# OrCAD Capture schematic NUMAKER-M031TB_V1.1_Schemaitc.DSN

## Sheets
1 Nu-Link2-Me: size A3; title: Nu-Link2-Me; rev: 1.0; company: CMHuang; note: Nu-Link2-Me
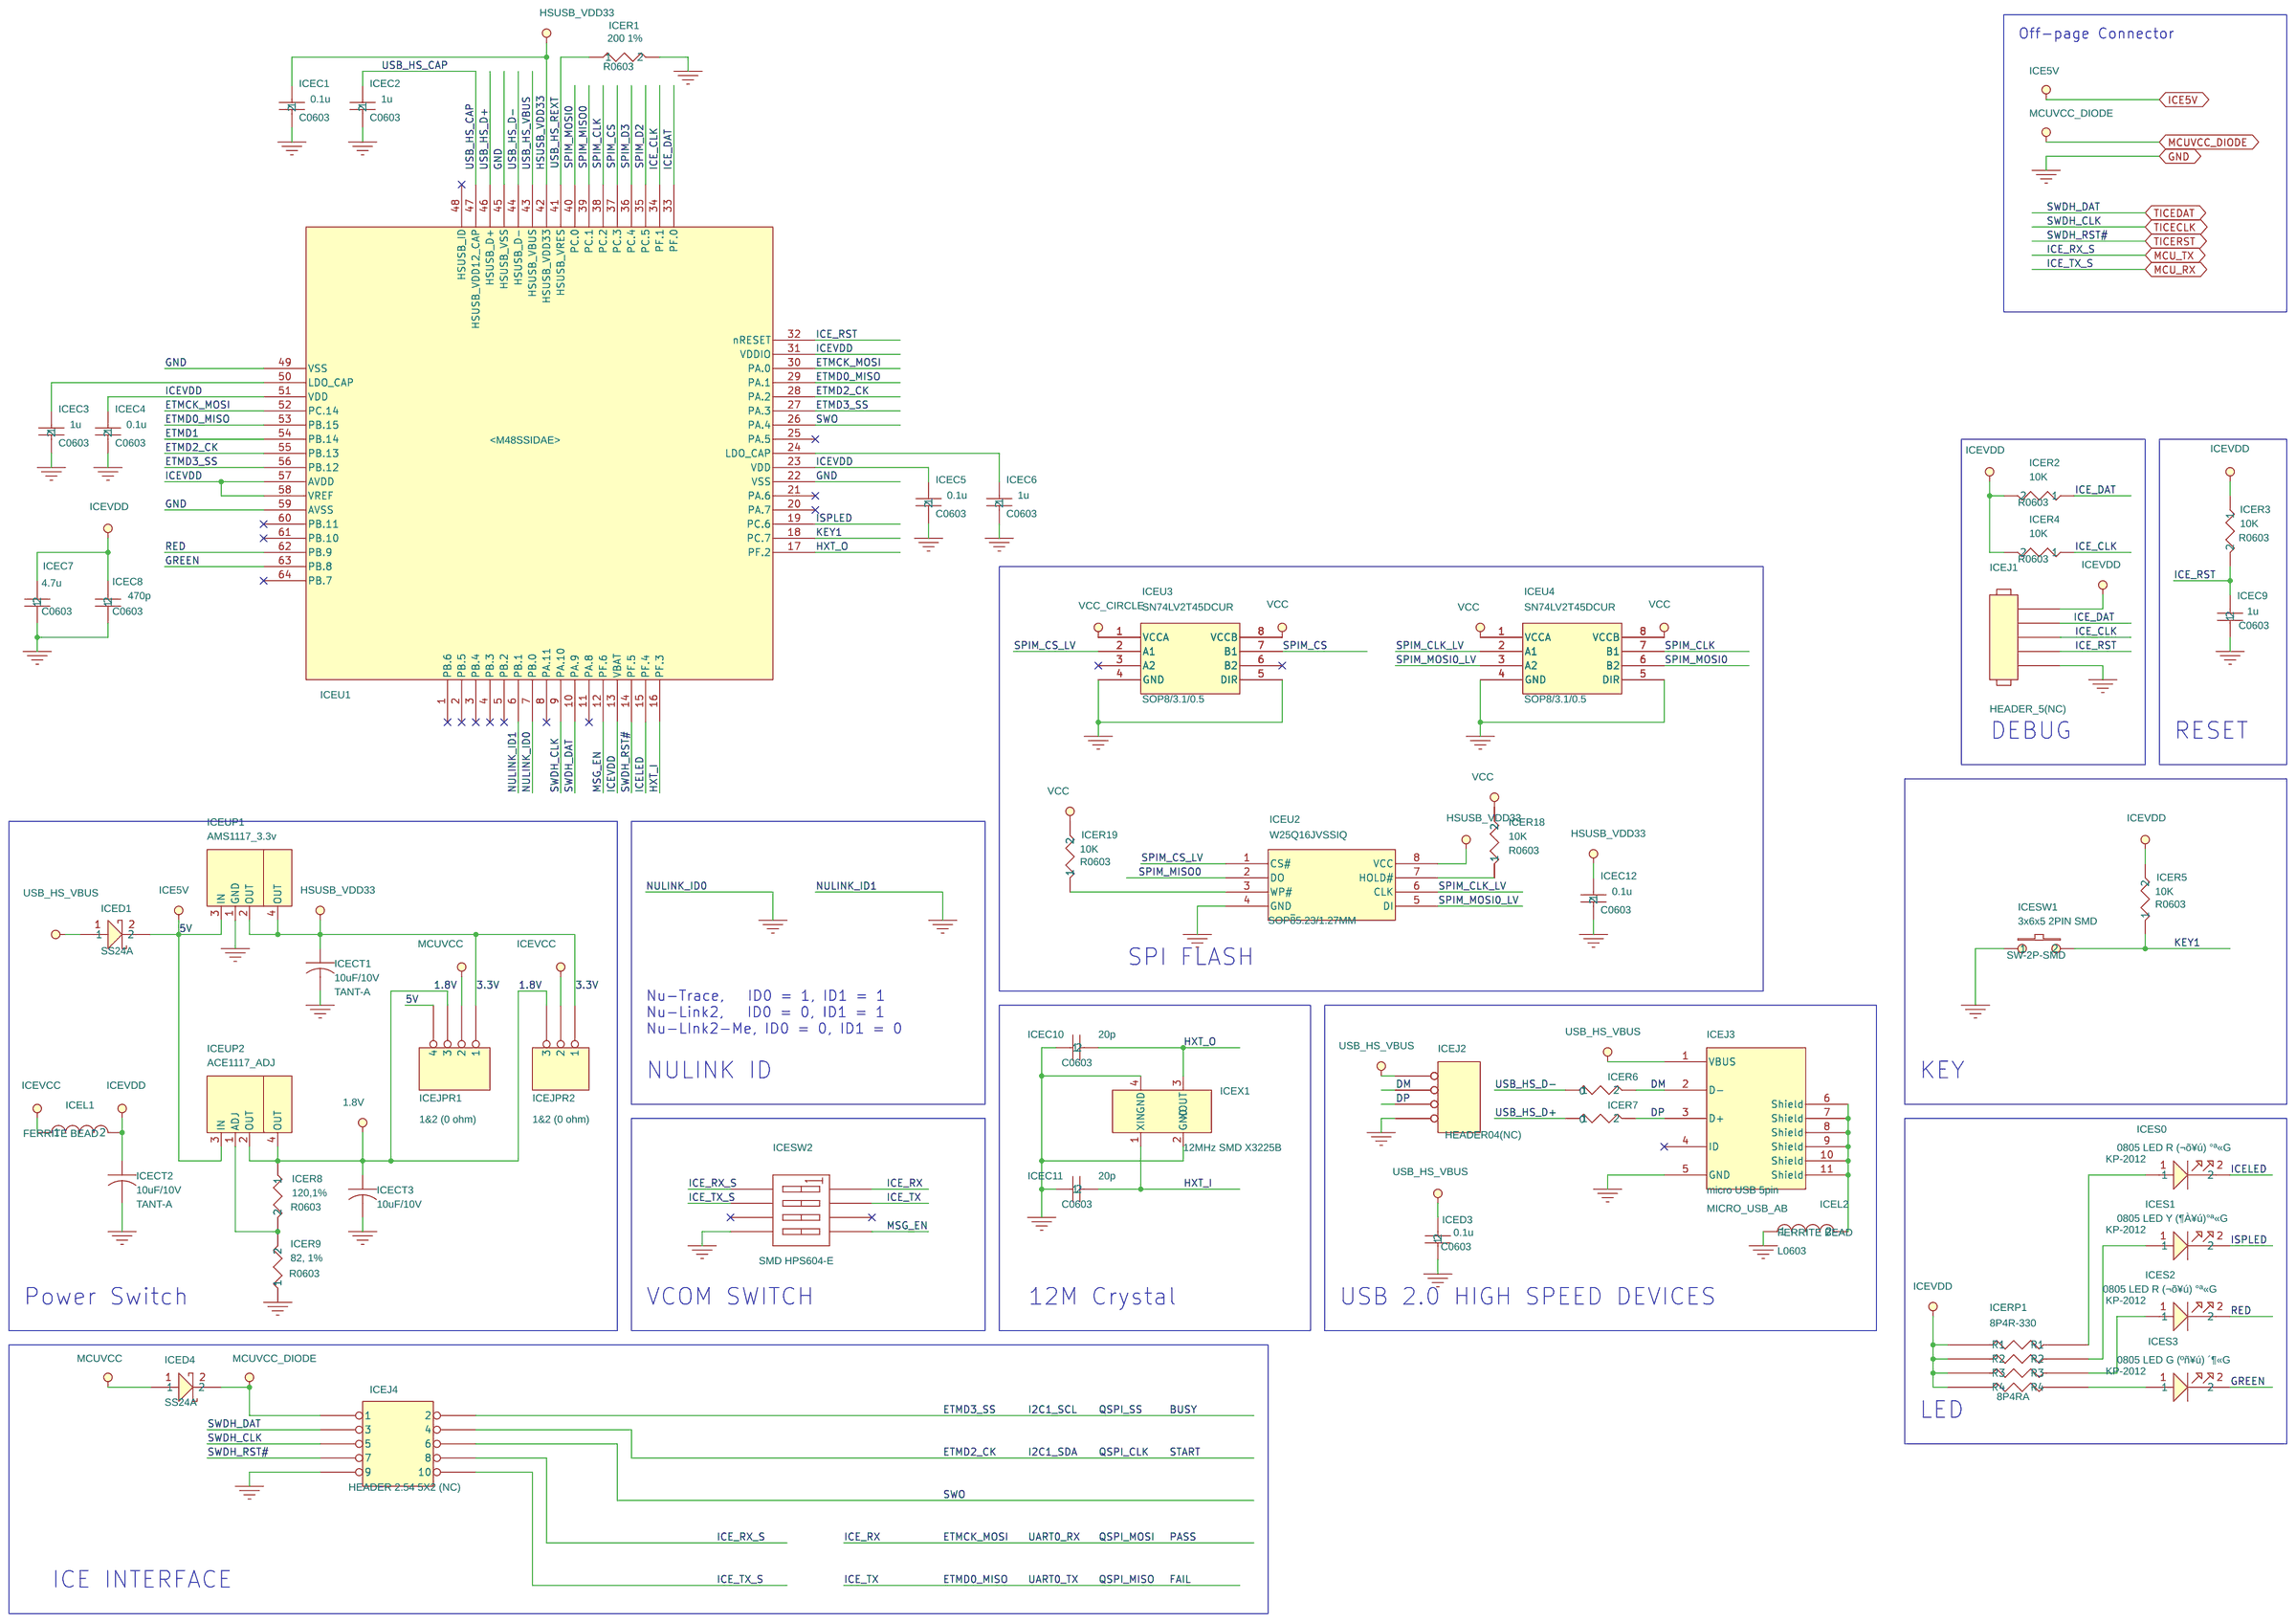
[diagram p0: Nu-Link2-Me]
2 M031TB0AE: size Custom; title: M031TB0AE; rev: v1.1; note: NuMaker-M031TB
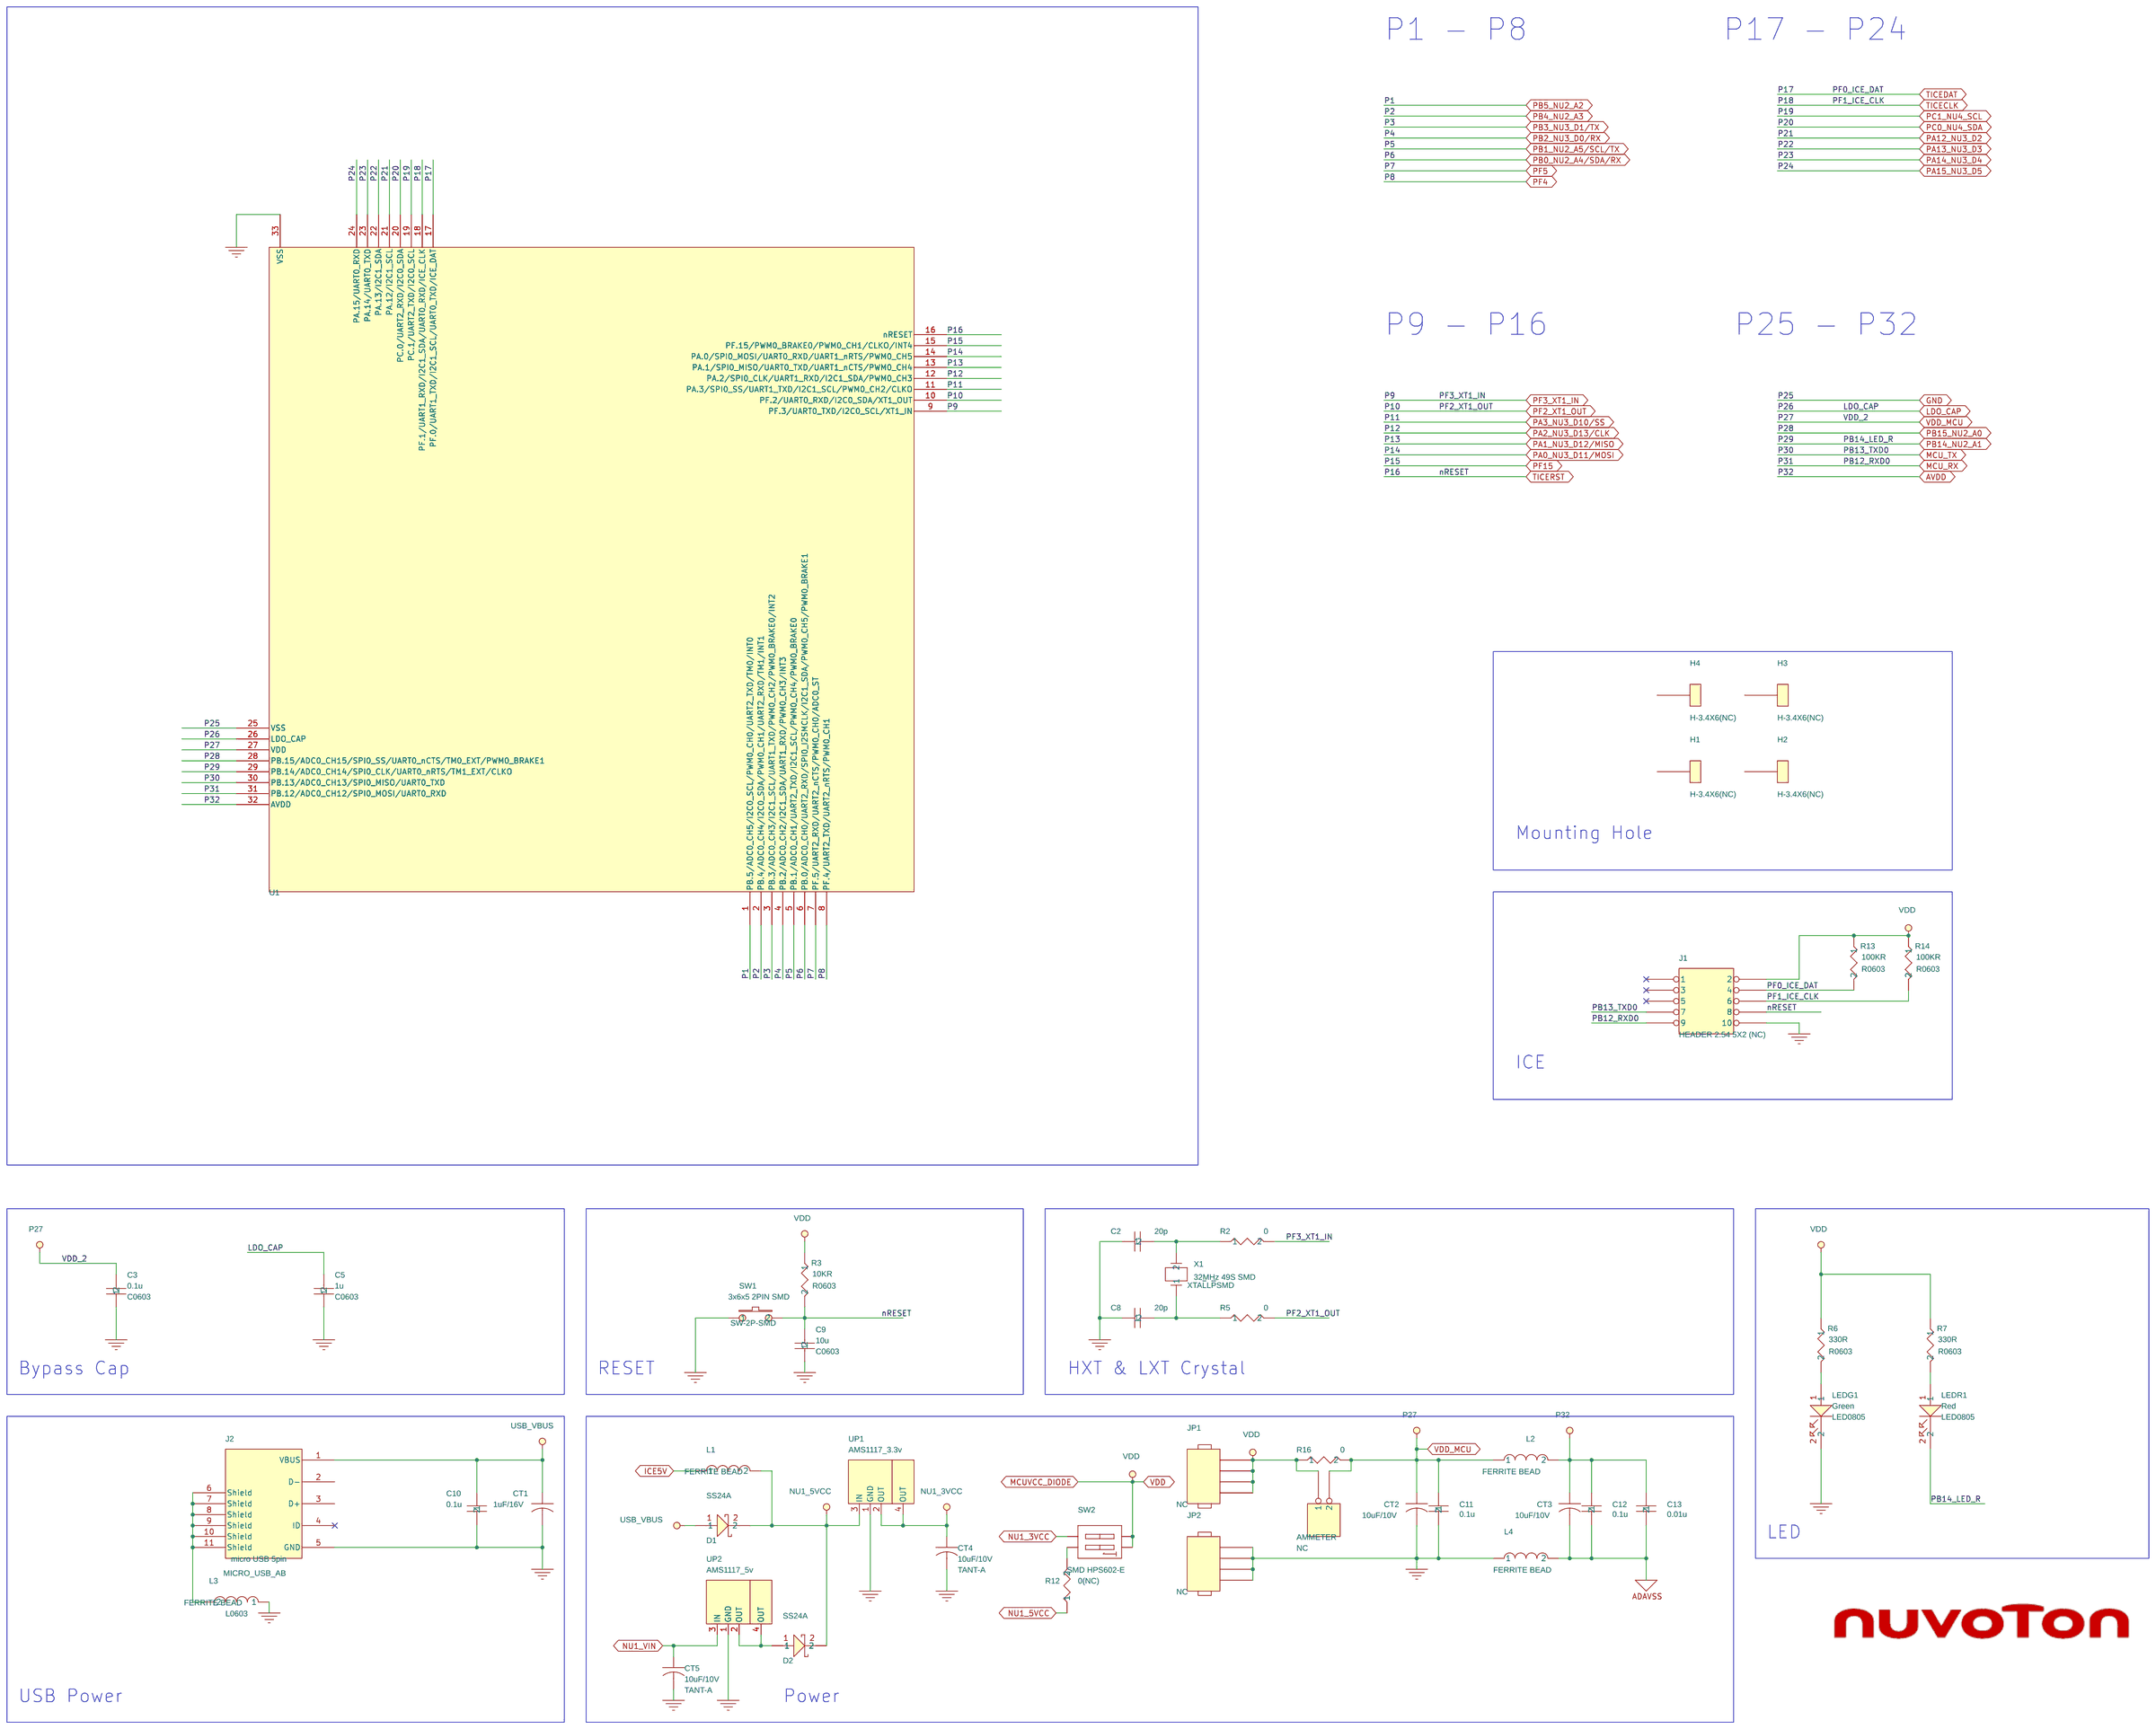
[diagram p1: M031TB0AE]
3 Ext. Connector: size Custom; title: Ext. Connector; rev: v1.1; note: NuMaker-M031TB
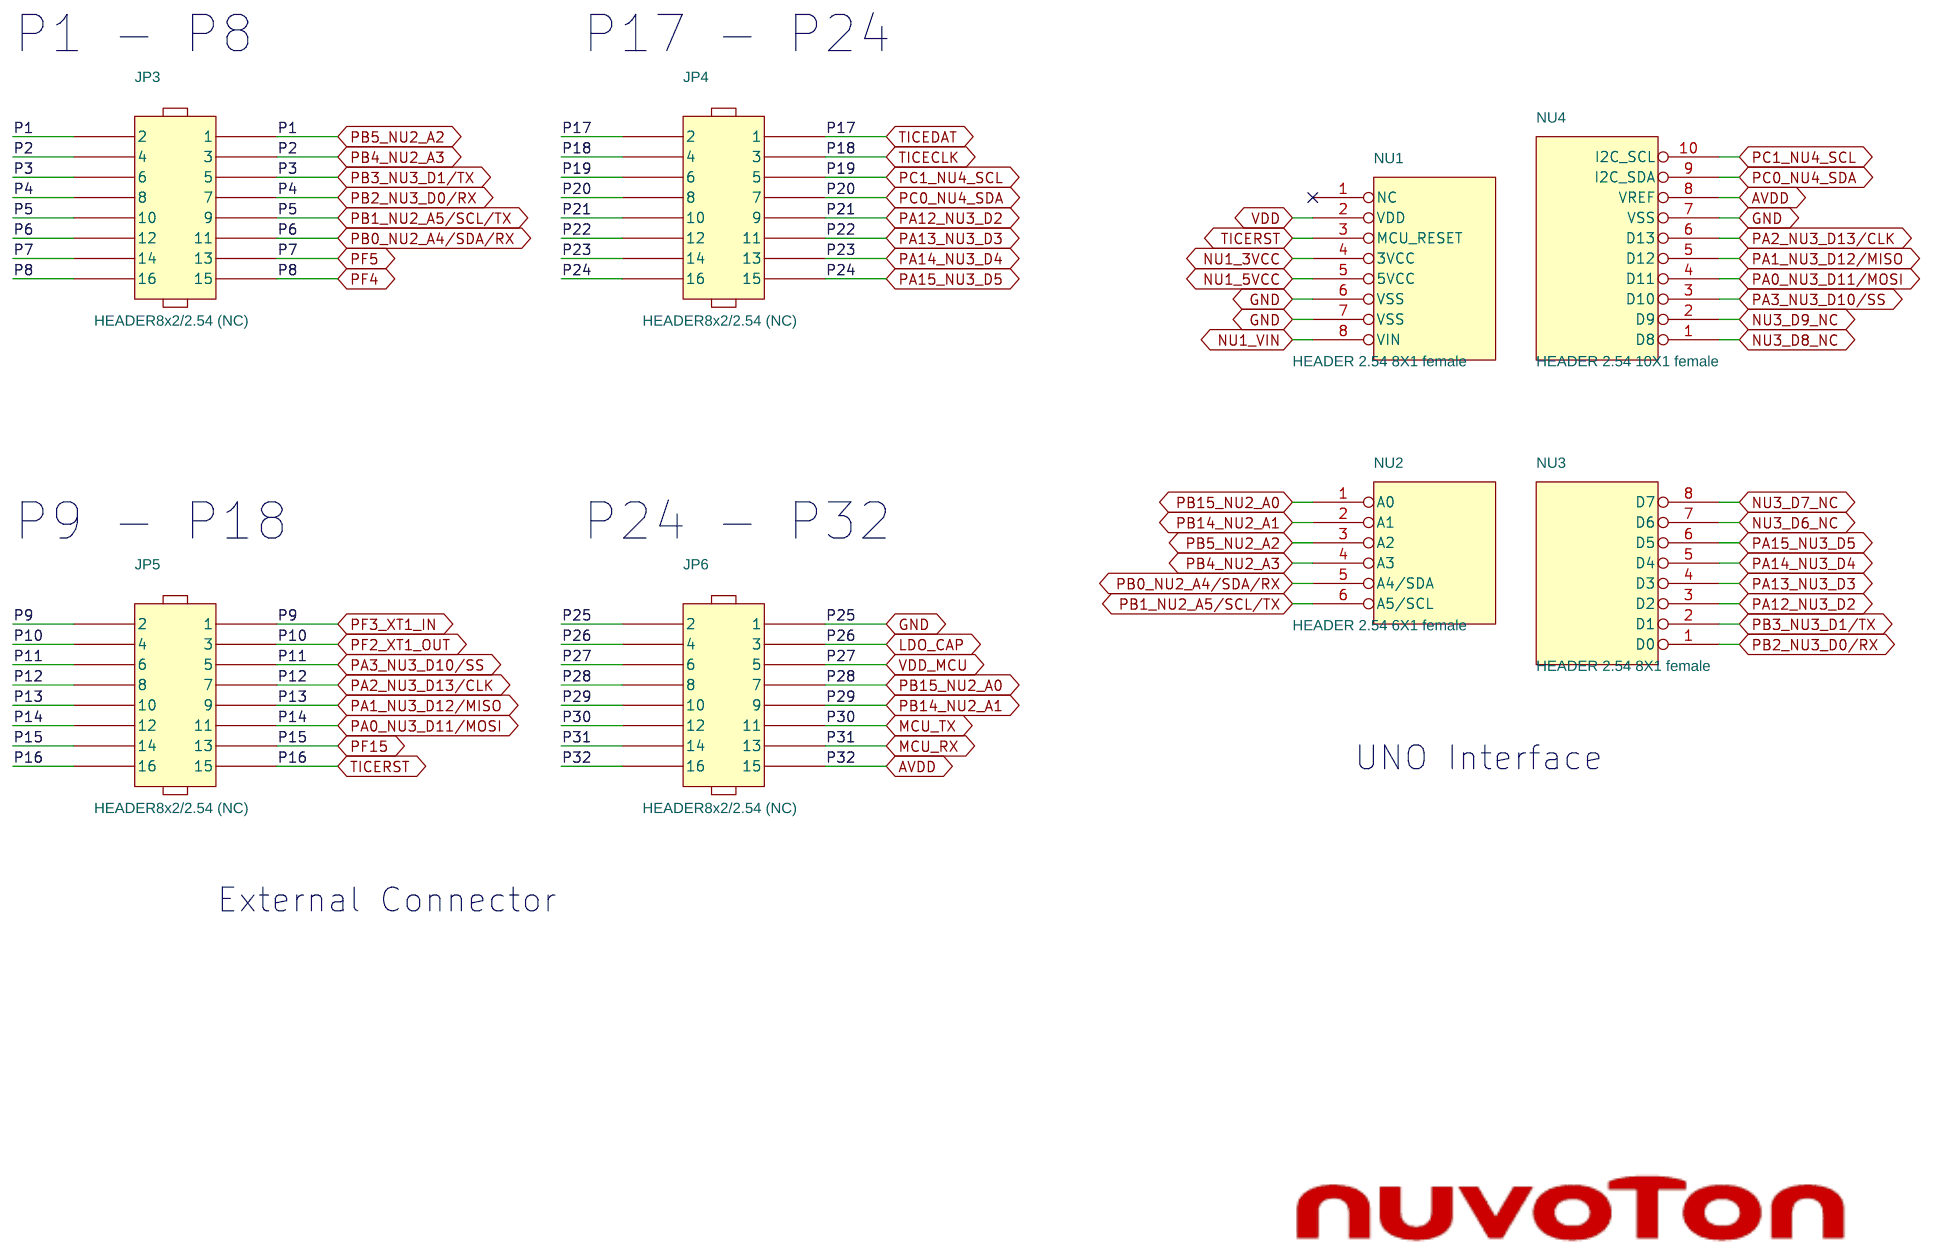
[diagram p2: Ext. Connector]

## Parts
sheet Ext. Connector
JP3  HEADER8x2/2.54 (NC)  [HEADER8x2/2.54]
JP4  HEADER8x2/2.54 (NC)  [HEADER8x2/2.54]
JP5  HEADER8x2/2.54 (NC)  [HEADER8x2/2.54]
JP6  HEADER8x2/2.54 (NC)  [HEADER8x2/2.54]
NU1  HEADER 2.54 8X1 female  [SIP-8P]
NU2  HEADER 2.54 6X1 female  [SIP-6P]
NU3  HEADER 2.54 8X1 female  [SIP-8P]
NU4  HEADER 2.54 10X1 female  [SIP-10P]
sheet M031TB0AE
AMMETER  NC  [HEADER2X1]
C2  20p  [C0603]
C3  0.1u  [C0603]
C5  1u  [C0603]
C8  20p  [C0603]
C9  10u  [C0603]
C10  0.1u  [C0603]
C11  0.1u  [C0603]
C12  0.1u  [C0603]
C13  0.01u  [C0603]
CT1  1uF/16V  [TANT-A]
CT2  10uF/10V  [TANT-A]
CT3  10uF/10V  [TANT-A]
CT4  10uF/10V  [TANT-A]
CT5  10uF/10V  [TANT-A]
D1  SS24A  [RB060L]
D2  SS24A  [RB060L]
H1  H-3.4X6(NC)  [H-3.4X6]
H2  H-3.4X6(NC)  [H-3.4X6]
H3  H-3.4X6(NC)  [H-3.4X6]
H4  H-3.4X6(NC)  [H-3.4X6]
J1  HEADER 2.54 5X2 (NC)  [HEADER5X2]
J2  micro USB 5pin  [MICRO_USB_AB]
JP1  NC  [header1x4]
JP2  NC  [header1x4]
L1  FERRITE BEAD  [L0603]
L2  FERRITE BEAD  [L0603]
L3  FERRITE BEAD  [L0603]
L4  FERRITE BEAD  [L0603]
LEDG1  Green  [LED0805]
LEDR1  Red  [LED0805]
R2  0  [R0603]
R3  10KR  [R0603]
R5  0  [R0603]
R6  330R  [R0603]
R7  330R  [R0603]
R12  0(NC)  [R0603]
R13  100KR  [R0603]
R14  100KR  [R0603]
R16  0  [R0603]
SW1  3x6x5 2PIN SMD  [SW-2P-SMD]
SW2  SMD HPS602-E  [SW1X2]
U1  M031TB0AE  [MCU_QFN_33_4x4]
UP1  AMS1117_3.3v  [SOT-223-1]
UP2  AMS1117_5v  [SOT-223-1]
X1  32MHz 49S SMD  [XTAL\LP\SMD]
sheet Nu-Link2-Me
ICEC1  0.1u  [C0603]
ICEC2  1u  [C0603]
ICEC3  1u  [C0603]
ICEC4  0.1u  [C0603]
ICEC5  0.1u  [C0603]
ICEC6  1u  [C0603]
ICEC7  4.7u  [C0603]
ICEC8  470p  [C0603]
ICEC9  1u  [C0603]
ICEC10  20p  [C0603]
ICEC11  20p  [C0603]
ICEC12  0.1u  [C0603]
ICECT1  10uF/10V  [TANT-A]
ICECT2  10uF/10V  [TANT-A]
ICECT3  10uF/10V  [TANT-A]
ICED1  SS24A  [RB060L]
ICED3  0.1u  [C0603]
ICED4  SS24A  [RB060L]
ICEJ1  HEADER_5(NC)  [HEADER5X1]
ICEJ2  HEADER04(NC)  [HEADER04]
ICEJ3  micro USB 5pin  [MICRO_USB_AB]
ICEJ4  HEADER 2.54 5X2 (NC)  [HEADER5X2]
ICEJPR1  1&2 (0 ohm)  [R0603X3]
ICEJPR2  1&2 (0 ohm)  [R0603X2]
ICEL1  FERRITE BEAD  [L0603]
ICEL2  FERRITE BEAD  [L0603]
ICER1  200 1%  [R0603]
ICER2  10K  [R0603]
ICER3  10K  [R0603]
ICER4  10K  [R0603]
ICER5  10K  [R0603]
ICER6  0  [R0603]
ICER7  0  [R0603]
ICER8  120,1%  [R0603]
ICER9  82, 1%  [R0603]
ICER18  10K  [R0603]
ICER19  10K  [R0603]
ICERP1  8P4R-330  [8P4RA]
ICES0  0805 LED R (¬õ¥ú) °ª«G  [KP-2012]
ICES1  0805 LED Y (¶À¥ú)°ª«G  [KP-2012]
ICES2  0805 LED R (¬õ¥ú) °ª«G  [KP-2012]
ICES3  0805 LED G (ºñ¥ú) ´¶«G  [KP-2012]
ICESW1  3x6x5 2PIN SMD  [SW-2P-SMD]
ICESW2  SMD HPS604-E  [SW1X4]
ICEU1  M48SSIDAE  [LQFP64_7x7_M48SSIDAE]
ICEU2  W25Q16JVSSIQ  [SOP8\5.23/1.27MM]
ICEU3  SN74LV2T45DCUR  [SOP8/3.1/0.5]
ICEU4  SN74LV2T45DCUR  [SOP8/3.1/0.5]
ICEUP1  AMS1117_3.3v  [SOT-223-1]
ICEUP2  ACE1117_ADJ  [SOT-223-1]
ICEX1  12MHz SMD X3225B  [CRYSTAL_SMD]

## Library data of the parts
JP3 = HEADER_8X2_3
JP4 = HEADER_8X2_1
JP5 = HEADER_8X2
JP6 = HEADER_8X2_2
NU1 = POWER_CONNECT_0
NU2 = ADC_CONNECT_0
NU3 = PWM0_CONNECT_0
NU4 = PWM1_CONNECT_1
AMMETER = HEADER_2
C2 = C_20p
C3 ICED3 = CAP-C_1: Package: 0603; element_no: C0004
C5 = CAP-C: Package: 0603; element_no: C0006
C8 = C_20p_1
C9 ICEC3 = CAP-C_2: Package: 0603; element_no: C0006
C10 = C_0.1u_2: element_no: C0004
C11 = C_0.1u: element_no: C0004
C12 = C_0.1u_1: element_no: C0004
C13 = C_0.1u_3: element_no: C0003
CT1 = C_1uF_16V
CT2-CT5 ICECT1-ICECT3 = C_10uF_10V
D1 ICED4 = D_SS24A
D2 ICED1 = D_SS24A_1
H1-H4 = TEST_POINT
ICEJ4 J1 = HEADER_5X2
ICEJ3 J2 = micro_USB_5pin_0
JP1 JP2 = HEADER_4
L1 = FERRITE_BEAD_3
ICEL2 L2 = FERRITE_BEAD_1
L3 = FERRITE_BEAD_2
ICEL1 L4 = FERRITE_BEAD
LEDG1 = LED_0_1: Package: KP-2012; Vendor: Kingbright
LEDR1 = LED_0: Package: KP-2012; Vendor: Kingbright
R2 = R_0_2
ICER4 R3 = R_0_3: Package: 0603
R5 = R_0_1
ICER18 R6 = R_0_6: Package: 0603
ICER8 R7 = R_0: Package: 0603
R12 = R_0_5
ICER3 R13 = R_0_4: Package: 0603
ICER19 R14 = R_0_7: Package: 0603
R16 = R_0_8
ICESW1 SW1 = SW_PUSHBUTTON_0
SW2 = SW_DIP-4_2
U1 = M031TB0AE
ICEUP1 UP1 UP2 = TO-247_Regulator_10
X1 = Xtal_12MHz
ICEC1 = CAP-C_11: Package: 0603; element_no: C0004
ICEC2 = CAP-C_9: Package: 0603; element_no: C0006
ICEC4 = CAP-C_10: Package: 0603; element_no: C0004
ICEC5 = CAP-C: Package: 0603; element_no: C0004
ICEC6 = CAP-C_12: Package: 0603; element_no: C0006
ICEC7 = CAP-C_5: Package: 0603
ICEC8 = CAP-C_6: Package: 0603
ICEC9 = CAP-C_7: Package: 0603; element_no: C0006
ICEC10 = CAP-C_3: Package: 0603
ICEC11 = CAP-C_4: Package: 0603
ICEC12 = CAP-C_8: Package: 0603; element_no: C0004
ICEJ1 = HEADER_5_v2
ICEJ2 = HEADER_4_v2
ICEJPR1 = HEADER_3_0
ICEJPR2 = HEADER_3
ICER1 = R_0_5: Package: 0603
ICER2 = R_0_1: Package: 0603
ICER5 = R_0_8: Package: 0603
ICER6 = R_33
ICER7 = R_33_1
ICER9 = R_0_2: Package: 0603
ICERP1 = R-PACK8_0
ICES0 = LED_0_3: Vendor: Kingbright
ICES1 = LED_0_2: Vendor: Kingbright
ICES2 = LED_0_1: Vendor: Kingbright
ICES3 = LED_0: Vendor: Kingbright
ICESW2 = SW_DIP-4_SM
ICEU1 = M487SIDAE_0: M487SIDAE: <M48SSIDAE>
ICEU2 = W25P10_20_40_SOIC_0: Package: SOP8; Vendor: WINBOND
ICEU3 ICEU4 = SN74LV2T45
ICEUP2 = TO-247_Regulator_0
ICEX1 = Crystal_SMD_1

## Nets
1.8V: ICECT3.1 ICEJPR1.3 ICEJPR2.3 ICER8.1 ICEUP2.2(OUT) ICEUP2.4(OUT)
3.3V: ICEC1.1 ICEC12.1 ICECT1.1 ICEJPR1.1 ICEJPR2.1 ICER18.2 ICER19.2 ICEU1.42(HSUSB_VDD33) ICEU2.8(VCC) ICEU3.1(VCCA) ICEU4.1(VCCA) ICEUP1.2(OUT) ICEUP1.4(OUT)
AVDD: C12.1 C13.1 CT3.1 JP6.15 JP6.16 L2.2 NU4.8(VREF) U1.32(AVDD)
AVSS: C12.2 C13.2 CT3.2 L4.2
GND: C2.1 C3.1 C5.1 C8.1 C9.1 C10.2 C11.2 CT1.2 CT2.2 CT4.2 CT5.2 ICEC1.2 ICEC2.2 ICEC3.2 ICEC4.2 ICEC5.2 ICEC6.2 ICEC7.1 ICEC8.1 ICEC9.1 ICEC10.1 ICEC11.1 ICEC12.2 ICECT1.2 ICECT2.2 ICECT3.2 ICED3.1 ICEJ1.5 ICEJ2.4 ICEJ3.5(GND) ICEJ4.9 ICEL2.1 ICER1.2 ICER9.1 ICESW1.1 ICESW2.4(A4) ICEU1.6(PB.1) ICEU1.7(PB.0) ICEU1.22(VSS) ICEU1.45(HSUSB_VSS) ICEU1.49(VSS) ICEU1.59(AVSS) ICEU2.4(GND) ICEU3.4(GND) ICEU3.5(DIR) ICEU4.4(GND) ICEU4.5(DIR) ICEUP1.1(GND) ICEX1.2(GND) ICEX1.4(GND) J1.10 J2.5(GND) JP2.1 JP2.2 JP2.3 JP2.4 JP6.1 JP6.2 L3.1 L4.1 LEDG1.2 NU1.6(VSS) NU1.7(VSS) NU4.7(VSS) SW1.1 U1.25(VSS) U1.33(VSS) UP1.1(GND) UP2.1(GND)
VDD: AMMETER.1 ICED4.2 ICEJ4.1 J1.2 JP1.1 JP1.2 JP1.3 JP1.4 NU1.2(VDD) R3.1 R6.1 R7.1 R13.1 R14.1 R16.1 SW2.3(B1) SW2.4(B2)
VDD_MCU: AMMETER.2 C3.2 C11.1 CT2.1 JP6.5 JP6.6 L2.1 R16.2 U1.27(VDD)
BUSY: ICEJ4.2 ICEU1.27(PA.3) ICEU1.56(PB.12)
DM: ICEJ2.2 ICEJ3.2(D-) ICER6.2
DP: ICEJ2.3 ICEJ3.3(D+) ICER7.2
ETMD1: ICEU1.54(PB.14)
ETMD2_CK: ICEJ4.4 ICEU1.28(PA.2) ICEU1.55(PB.13)
GREEN: ICES3.2 ICEU1.63(PB.8)
HXT_I: ICEC11.2 ICEU1.16(PF.3) ICEX1.1(XIN)
HXT_O: ICEC10.2 ICEU1.17(PF.2) ICEX1.3(XOUT)
ICE5V: ICED1.2 ICEJPR1.4 ICEUP1.3(IN) ICEUP2.3(IN) L1.1
ICE_CLK: ICEJ1.3 ICER4.1 ICEU1.34(PF.1)
ICE_DAT: ICEJ1.2 ICER2.1 ICEU1.33(PF.0)
ICE_RST: ICEC9.2 ICEJ1.4 ICER3.2 ICEU1.32(nRESET)
ICE_RX: ICESW2.8(B1) ICEU1.30(PA.0) ICEU1.52(PC.14)
ICE_TX: ICESW2.7(B2) ICEU1.29(PA.1) ICEU1.53(PB.15)
ICELED: ICES0.2 ICEU1.15(PF.4)
ICEVCC: ICEJPR2.2 ICEL1.1
ICEVDD: ICEC4.1 ICEC5.1 ICEC7.2 ICEC8.2 ICECT2.1 ICEJ1.1 ICEL1.2 ICER2.2 ICER3.1 ICER4.2 ICER5.2 ICERP1.1(R1) ICERP1.3(R2) ICERP1.5(R3) ICERP1.7(R4) ICEU1.13(VBAT) ICEU1.23(VDD) ICEU1.31(VDDIO) ICEU1.51(VDD) ICEU1.57(AVDD) ICEU1.58(VREF) ICEU3.8(VCCB) ICEU4.8(VCCB)
ISPLED: ICES1.2 ICEU1.19(PC.6)
KEY1: ICER5.1 ICESW1.2 ICEU1.18(PC.7)
LDO_CAP: C5.2 JP6.3 JP6.4 U1.26(LDO_CAP)
MCU_RX: ICEJ4.10 ICESW2.2(A2) J1.9 JP6.13 JP6.14 U1.31(PB.12/ADC0_CH12/SPI0_MOSI/UART0_RXD)
MCU_TX: ICEJ4.8 ICESW2.1(A1) J1.7 JP6.11 JP6.12 U1.30(PB.13/ADC0_CH13/SPI0_MISO/UART0_TXD)
MCUVCC: ICED4.1 ICEJPR1.2
MSG_EN: ICESW2.5(B4) ICEU1.12(PF.6)
NU1_3VCC: CT4.1 NU1.4(3VCC) SW2.2(A2) UP1.2(OUT) UP1.4(OUT)
NU1_5VCC: D1.2 D2.2 L1.2 NU1.5(5VCC) R12.1 UP1.3(IN)
NU1_VIN: CT5.1 NU1.8(VIN) UP2.3(IN)
NU3_D6_NC: NU3.7(D6)
NU3_D7_NC: NU3.8(D7)
NU3_D8_NC: NU4.1(D8)
NU3_D9_NC: NU4.2(D9)
PA0_NU3_D11/MOSI: JP5.11 JP5.12 NU4.4(D11) U1.14(PA.0/SPI0_MOSI/UART0_RXD/UART1_nRTS/PWM0_CH5)
PA1_NU3_D12/MISO: JP5.9 JP5.10 NU4.5(D12) U1.13(PA.1/SPI0_MISO/UART0_TXD/UART1_nCTS/PWM0_CH4)
PA2_NU3_D13/CLK: JP5.7 JP5.8 NU4.6(D13) U1.12(PA.2/SPI0_CLK/UART1_RXD/I2C1_SDA/PWM0_CH3)
PA3_NU3_D10/SS: JP5.5 JP5.6 NU4.3(D10) U1.11(PA.3/SPI0_SS/UART1_TXD/I2C1_SCL/PWM0_CH2/CLKO)
PA12_NU3_D2: JP4.9 JP4.10 NU3.3(D2) U1.21(PA.12/I2C1_SCL)
PA13_NU3_D3: JP4.11 JP4.12 NU3.4(D3) U1.22(PA.13/I2C1_SDA)
PA14_NU3_D4: JP4.13 JP4.14 NU3.5(D4) U1.23(PA.14/UART0_TXD)
PA15_NU3_D5: JP4.15 JP4.16 NU3.6(D5) U1.24(PA.15/UART0_RXD)
PB0_NU2_A4/SDA/RX: JP3.11 JP3.12 NU2.5(A4/SDA) U1.6(PB.0/ADC0_CH0/UART2_RXD/SPI0_I2SMCLK/I2C1_SDA/PWM0_CH5/PWM0_BRAKE1)
PB1_NU2_A5/SCL/TX: JP3.9 JP3.10 NU2.6(A5/SCL) U1.5(PB.1/ADC0_CH1/UART2_TXD/I2C1_SCL/PWM0_CH4/PWM0_BRAKE0)
PB2_NU3_D0/RX: JP3.7 JP3.8 NU3.1(D0) U1.4(PB.2/ADC0_CH2/I2C1_SDA/UART1_RXD/PWM0_CH3/INT3)
PB3_NU3_D1/TX: JP3.5 JP3.6 NU3.2(D1) U1.3(PB.3/ADC0_CH3/I2C1_SCL/UART1_TXD/PWM0_CH2/PWM0_BRAKE0/INT2)
PB4_NU2_A3: JP3.3 JP3.4 NU2.4(A3) U1.2(PB.4/ADC0_CH4/I2C0_SDA/PWM0_CH1/UART2_RXD/TM1/INT1)
PB5_NU2_A2: JP3.1 JP3.2 NU2.3(A2) U1.1(PB.5/ADC0_CH5/I2C0_SCL/PWM0_CH0/UART2_TXD/TM0/INT0)
PB14_NU2_A1: JP6.9 JP6.10 LEDR1.2 NU2.2(A1) U1.29(PB.14/ADC0_CH14/SPI0_CLK/UART0_nRTS/TM1_EXT/CLKO)
PB15_NU2_A0: JP6.7 JP6.8 NU2.1(A0) U1.28(PB.15/ADC0_CH15/SPI0_SS/UART0_nCTS/TM0_EXT/PWM0_BRAKE1)
PC0_NU4_SDA: JP4.7 JP4.8 NU4.9(I2C_SDA) U1.20(PC.0/UART2_RXD/I2C0_SDA)
PC1_NU4_SCL: JP4.5 JP4.6 NU4.10(I2C_SCL) U1.19(PC.1/UART2_TXD/I2C0_SCL)
PF2_XT1_OUT: JP5.3 JP5.4 R5.2 U1.10(PF.2/UART0_RXD/I2C0_SDA/XT1_OUT)
PF3_XT1_IN: JP5.1 JP5.2 R2.2 U1.9(PF.3/UART0_TXD/I2C0_SCL/XT1_IN)
PF4: JP3.15 JP3.16 U1.8(PF.4/UART2_TXD/UART2_nRTS/PWM0_CH1)
PF5: JP3.13 JP3.14 U1.7(PF.5/UART2_RXD/UART2_nCTS/PWM0_CH0/ADC0_ST)
PF15: JP5.13 JP5.14 U1.15(PF.15/PWM0_BRAKE0/PWM0_CH1/CLKO/INT4)
RED: ICES2.2 ICEU1.62(PB.9)
SPIM_CLK: ICEU1.38(PC.2) ICEU4.7(B1)
SPIM_CLK_LV: ICEU2.6(CLK) ICEU4.2(A1)
SPIM_CS: ICEU1.37(PC.3) ICEU3.7(B1)
SPIM_CS_LV: ICEU2.1(CS#) ICEU3.2(A1)
SPIM_D2: ICEU1.35(PC.5)
SPIM_D3: ICEU1.36(PC.4)
SPIM_MISO0: ICEU1.39(PC.1) ICEU2.2(DO)
SPIM_MOSI0: ICEU1.40(PC.0) ICEU4.6(B2)
SPIM_MOSI0_LV: ICEU2.5(DI) ICEU4.3(A2)
SWO: ICEJ4.6 ICEU1.26(PA.4)
TICECLK: ICEJ4.5 ICEU1.9(PA.10) J1.6 JP4.3 JP4.4 R14.2 U1.18(PF.1/UART1_RXD/I2C1_SDA/UART0_RXD/ICE_CLK)
TICEDAT: ICEJ4.3 ICEU1.10(PA.9) J1.4 JP4.1 JP4.2 R13.2 U1.17(PF.0/UART1_TXD/I2C1_SCL/UART0_TXD/ICE_DAT)
TICERST: C9.2 ICEJ4.7 ICEU1.14(PF.5) J1.8 JP5.15 JP5.16 NU1.3(MCU_RESET) R3.2 SW1.2 U1.16(nRESET)
USB_HS_CAP: ICEC2.1 ICEU1.47(HSUSB_VDD12_CAP)
USB_HS_D+: ICER7.1 ICEU1.46(HSUSB_D+)
USB_HS_D-: ICER6.1 ICEU1.44(HSUSB_D-)
USB_HS_REXT: ICER1.1 ICEU1.41(HSUSB_VRES)
USB_HS_VBUS: ICED1.1 ICED3.2 ICEJ2.1 ICEJ3.1(VBUS) ICEU1.43(HSUSB_VBUS)
USB_VBUS: C10.1 CT1.1 D1.1 J2.1(VBUS)
N16825237: LEDG1.1 R6.2
N16825240: LEDR1.1 R7.2
N16840819: ICEC6.1 ICEU1.24(LDO_CAP)
N16840960: ICEC3.1 ICEU1.50(LDO_CAP)
N17019924: ICER8.2 ICER9.2 ICEUP2.1(ADJ)
N17029977: ICERP1.8(R4) ICES3.1
N17029979: ICERP1.6(R3) ICES2.1
N17030004: ICERP1.4(R2) ICES1.1
N17030010: ICERP1.2(R1) ICES0.1
N17042369: ICEJ3.6(Shield) ICEJ3.7(Shield) ICEJ3.8(Shield) ICEJ3.9(Shield) ICEJ3.10(Shield) ICEJ3.11(Shield) ICEL2.2
N17110356: J2.6(Shield) J2.7(Shield) J2.8(Shield) J2.9(Shield) J2.10(Shield) J2.11(Shield) L3.2
N17125028: R12.2 SW2.1(A1)
N17155328: ICER18.1 ICEU2.7(HOLD#)
N17155343: ICER19.1 ICEU2.3(WP#)
N17159369: C8.2 R5.1 X1.1
N17159371: C2.2 R2.1 X1.2
N17167442: D2.1 UP2.2(OUT) UP2.4(OUT)

Not connected (* = marked no-connect by the designer): H1 1; H2 1; H3 1; H4 1; ICEJ3 4(ID)*; ICESW2 3(A3)* 6(B3)*; ICEU1 1(PB.6)* 2(PB.5)* 3(PB.4)* 4(PB.3)* 5(PB.2)* 8(PA.11)* 11(PA.8)* 20(PA.7)* 21(PA.6)* 25(PA.5)* 48(HSUSB_ID)* 60(PB.11)* 61(PB.10)* 64(PB.7)*; ICEU3 3(A2)* 6(B2)*; J1 1* 3* 5*; J2 2(D-) 3(D+) 4(ID)*; NU1 1(NC)*

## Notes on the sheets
sheet 1
- Off-page Connector
- DEBUG
- RESET
- SPI FLASH
- Nu-Trace,   ID0 = 1, ID1 = 1
  Nu-Link2,   ID0 = 0, ID1 = 1
  Nu-LInk2-Me, ID0 = 0, ID1 = 0
- NULINK ID
- KEY
- Power Switch
- VCOM SWITCH
- 12M Crystal
- USB 2.0 HIGH SPEED DEVICES
- LED
- ICE INTERFACE
sheet 2
- P1 - P8
- P17 - P24
- P9 - P16
- P25 - P32
- Mounting Hole
- ICE
- Bypass Cap
- RESET
- HXT & LXT Crystal
- LED
- USB Power
- Power
sheet 3
- P1 - P8
- P17 - P24
- P9 - P18
- P24 - P32
- UNO Interface
- External Connector
